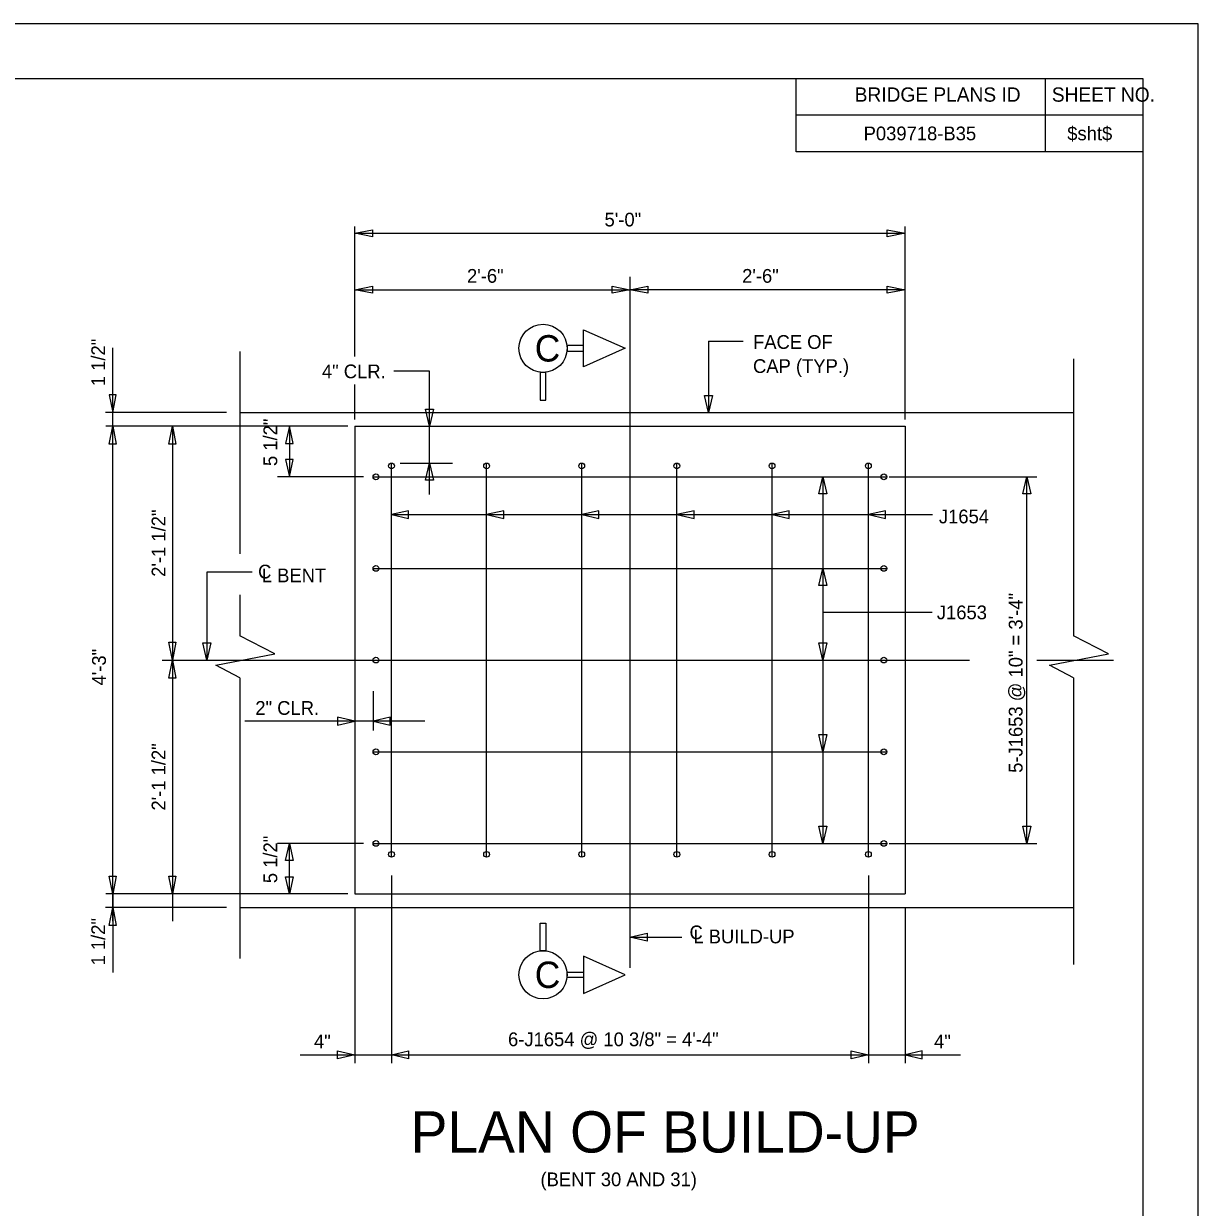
# Model space of a CAD drawing. Extents: x -133.1 to -97, y -58.4 to -36.4.
# Drawn here: x -107.81 to -97.14, y -47.16 to -36.4 of the extents above; entities that cross this region are included whole.
import ezdxf

# ---------------------------------------------------------------- set-up
doc = ezdxf.new("R2010")
doc.units = 0
for name, color, linetype in [('BR_AUTO DIMENSION', 7, 'Continuous'), ('BR_BORDER LINES', 7, 'Continuous'), ('BR_CENTER LINES', 7, 'Continuous'), ('BR_CONCRETE', 7, 'Continuous'), ('BR_REBAR', 7, 'Continuous'), ('BR_TEXT', 7, 'Continuous'), ('Default', 7, 'Continuous'), ('Level 31', 7, 'Continuous')]:
    doc.layers.add(name, color=color, linetype=linetype)

msp = doc.modelspace()

# ---------------------------------------------------------------- linework, layer by layer
at = {"layer": 'BR_AUTO DIMENSION'}
for p, q in [((-104.806, -39.424), (-104.806, -38.242)), ((-104.806, -38.304), (-99.806, -38.304)), ((-99.806, -39.997), (-99.806, -38.242)), ((-102.306, -38.699), (-102.306, -39.063)), ((-104.806, -38.817), (-102.306, -38.817)), ((-99.806, -38.817), (-102.306, -38.817)), ((-107.005, -40.059), (-107.005, -39.345)), ((-101.592, -39.284), (-101.592, -39.934)), ((-101.592, -39.284), (-101.275, -39.284)), ((-104.126, -39.559), (-104.45, -39.559)), ((-104.126, -40.68), (-104.126, -39.559)), ((-104.806, -39.997), (-104.806, -39.678)), ((-107.005, -44.559), (-107.005, -39.809)), ((-105.97, -39.934), (-107.071, -39.934)), ((-104.868, -40.059), (-107.067, -40.059)), ((-106.463, -40.059), (-106.463, -42.184)), ((-105.4, -40.059), (-105.4, -40.518)), ((-104.394, -40.393), (-103.919, -40.393)), ((-104.727, -40.518), (-105.507, -40.518)), ((-100.552, -40.518), (-100.552, -43.851)), ((-99.951, -40.518), (-98.608, -40.518)), ((-98.7, -43.851), (-98.7, -40.518)), ((-104.472, -40.862), (-99.555, -40.862)), ((-106.149, -41.385), (-106.149, -42.184)), ((-105.737, -41.385), (-106.149, -41.385)), ((-100.552, -41.748), (-99.559, -41.748)), ((-106.52, -42.184), (-106.384, -42.184)), ((-106.463, -42.184), (-106.463, -44.559)), ((-104.639, -42.468), (-104.639, -42.823)), ((-104.17, -42.739), (-105.805, -42.739)), ((-104.727, -43.851), (-105.507, -43.851)), ((-105.4, -44.309), (-105.4, -43.851)), ((-99.951, -43.851), (-98.608, -43.851)), ((-104.472, -44.142), (-104.472, -45.847)), ((-100.139, -44.142), (-100.139, -45.847)), ((-104.868, -44.309), (-107.067, -44.309)), ((-107.005, -44.309), (-107.005, -45.023)), ((-105.97, -44.434), (-107.071, -44.434)), ((-104.806, -44.434), (-104.806, -45.847)), ((-99.806, -44.434), (-99.806, -45.847)), ((-102.306, -44.704), (-101.834, -44.704)), ((-105.302, -45.772), (-99.301, -45.772))]:
    msp.add_line(p, q, dxfattribs=at)
for points in [[(-104.643, -38.336), (-104.806, -38.304), (-104.643, -38.273)], [(-99.968, -38.273), (-99.806, -38.304), (-99.968, -38.336)], [(-104.643, -38.848), (-104.806, -38.817), (-104.643, -38.785)], [(-102.468, -38.785), (-102.306, -38.817), (-102.468, -38.848)], [(-102.143, -38.848), (-102.306, -38.817), (-102.143, -38.785)], [(-99.968, -38.785), (-99.806, -38.817), (-99.968, -38.848)], [(-107.036, -39.772), (-107.005, -39.934), (-106.974, -39.772)], [(-101.556, -39.778), (-101.592, -39.934), (-101.628, -39.778)], [(-104.09, -39.903), (-104.126, -40.059), (-104.162, -39.903)], [(-107.036, -40.222), (-107.005, -40.059), (-106.974, -40.222)], [(-106.494, -40.222), (-106.463, -40.059), (-106.432, -40.222)], [(-105.364, -40.215), (-105.4, -40.059), (-105.436, -40.215)], [(-105.436, -40.362), (-105.4, -40.518), (-105.364, -40.362)], [(-104.162, -40.549), (-104.126, -40.393), (-104.09, -40.549)], [(-100.588, -40.674), (-100.552, -40.518), (-100.516, -40.674)], [(-98.736, -40.674), (-98.7, -40.518), (-98.664, -40.674)], [(-104.316, -40.826), (-104.472, -40.862), (-104.316, -40.898)], [(-103.452, -40.826), (-103.608, -40.862), (-103.452, -40.898)], [(-102.587, -40.826), (-102.743, -40.862), (-102.587, -40.898)], [(-101.723, -40.826), (-101.879, -40.862), (-101.723, -40.898)], [(-100.858, -40.826), (-101.014, -40.862), (-100.858, -40.898)], [(-99.983, -40.826), (-100.139, -40.862), (-99.983, -40.898)], [(-100.588, -41.507), (-100.552, -41.351), (-100.516, -41.507)], [(-106.432, -42.022), (-106.463, -42.184), (-106.494, -42.022)], [(-106.113, -42.028), (-106.149, -42.184), (-106.185, -42.028)], [(-100.516, -42.028), (-100.552, -42.184), (-100.588, -42.028)], [(-106.494, -42.347), (-106.463, -42.184), (-106.432, -42.347)], [(-104.962, -42.775), (-104.806, -42.739), (-104.962, -42.703)], [(-104.483, -42.703), (-104.639, -42.739), (-104.483, -42.775)], [(-100.516, -42.862), (-100.552, -43.018), (-100.588, -42.862)], [(-100.516, -43.695), (-100.552, -43.851), (-100.588, -43.695)], [(-98.664, -43.695), (-98.7, -43.851), (-98.736, -43.695)], [(-105.436, -44.007), (-105.4, -43.851), (-105.364, -44.007)], [(-106.974, -44.147), (-107.005, -44.309), (-107.036, -44.147)], [(-106.432, -44.147), (-106.463, -44.309), (-106.494, -44.147)], [(-105.364, -44.153), (-105.4, -44.309), (-105.436, -44.153)], [(-107.036, -44.597), (-107.005, -44.434), (-106.974, -44.597)], [(-102.15, -44.74), (-102.306, -44.704), (-102.15, -44.668)], [(-104.962, -45.736), (-104.806, -45.772), (-104.962, -45.808)], [(-104.316, -45.808), (-104.472, -45.772), (-104.316, -45.736)], [(-100.295, -45.736), (-100.139, -45.772), (-100.295, -45.808)], [(-99.65, -45.736), (-99.806, -45.772), (-99.65, -45.808)]]:
    msp.add_lwpolyline(points, close=True, dxfattribs=at)
at = {"layer": 'BR_BORDER LINES'}
for p, q in [((-97.642, -36.899), (-131.308, -36.899)), ((-100.794, -37.565), (-100.794, -36.899)), ((-98.528, -37.565), (-98.528, -36.899)), ((-97.642, -57.899), (-97.642, -36.899)), ((-100.794, -37.228), (-97.642, -37.228)), ((-98.528, -37.228), (-97.642, -37.228)), ((-97.642, -37.565), (-100.794, -37.565))]:
    msp.add_line(p, q, dxfattribs=at)
at = {"layer": 'BR_CENTER LINES'}
for p, q in [((-102.306, -39.063), (-102.306, -44.981)), ((-106.555, -42.184), (-99.221, -42.184)), ((-98.609, -42.184), (-97.913, -42.184))]:
    msp.add_line(p, q, dxfattribs=at)
at = {"layer": 'BR_CONCRETE'}
for p, q in [((-105.85, -39.934), (-98.276, -39.934)), ((-104.806, -40.059), (-99.806, -40.059)), ((-104.806, -40.059), (-104.806, -44.309)), ((-99.806, -40.059), (-99.806, -44.309)), ((-104.806, -44.309), (-99.806, -44.309)), ((-105.85, -44.434), (-98.276, -44.434))]:
    msp.add_line(p, q, dxfattribs=at)
at = {"layer": 'BR_REBAR'}
for p, q in [((-104.472, -43.976), (-104.472, -40.393)), ((-103.608, -43.976), (-103.608, -40.393)), ((-102.743, -43.976), (-102.743, -40.393)), ((-101.879, -43.976), (-101.879, -40.393)), ((-101.014, -43.976), (-101.014, -40.393)), ((-100.139, -43.976), (-100.139, -40.393)), ((-104.639, -40.518), (-99.972, -40.518)), ((-104.639, -41.351), (-99.972, -41.351)), ((-104.639, -42.184), (-99.972, -42.184)), ((-104.639, -43.018), (-99.972, -43.018)), ((-104.639, -43.851), (-99.972, -43.851))]:
    msp.add_line(p, q, dxfattribs=at)
for centre, radius in [((-104.472, -40.419), 0.0261), ((-103.608, -40.419), 0.0261), ((-102.743, -40.419), 0.0261), ((-101.879, -40.419), 0.0261), ((-101.014, -40.419), 0.0261), ((-100.139, -40.419), 0.0261), ((-104.613, -40.518), 0.026), ((-99.998, -40.518), 0.026), ((-104.613, -41.351), 0.026), ((-99.998, -41.351), 0.026), ((-104.613, -42.184), 0.026), ((-99.998, -42.184), 0.026), ((-104.613, -43.018), 0.026), ((-99.998, -43.018), 0.026), ((-104.613, -43.851), 0.026), ((-99.998, -43.851), 0.026), ((-104.472, -43.95), 0.0261), ((-103.608, -43.95), 0.0261), ((-102.743, -43.95), 0.0261), ((-101.879, -43.95), 0.0261), ((-101.014, -43.95), 0.0261), ((-100.139, -43.95), 0.0261)]:
    msp.add_circle(centre, radius, dxfattribs=at)
at = {"layer": 'BR_TEXT'}
for points in [[(-102.726, -39.182), (-102.35, -39.35), (-102.726, -39.519)], [(-102.876, -39.375), (-102.726, -39.375), (-102.726, -39.325), (-102.876, -39.325)], [(-103.12, -39.82), (-103.07, -39.82), (-103.07, -39.569), (-103.12, -39.569)], [(-103.12, -44.576), (-103.07, -44.576), (-103.07, -44.826), (-103.12, -44.826)], [(-102.726, -45.214), (-102.35, -45.045), (-102.726, -44.876)], [(-102.876, -45.02), (-102.726, -45.02), (-102.726, -45.07), (-102.876, -45.07)]]:
    msp.add_lwpolyline(points, close=True, dxfattribs=at)
for centre in [(-103.095, -39.35), (-103.095, -45.045)]:
    msp.add_circle(centre, 0.219, dxfattribs=at)
at = {"layer": 'Default'}
for p, q in [((-105.85, -39.38), (-105.85, -41.219)), ((-98.276, -39.445), (-98.276, -41.963)), ((-105.85, -41.591), (-105.85, -41.963)), ((-105.85, -42.346), (-105.85, -44.896)), ((-98.276, -42.346), (-98.276, -44.952))]:
    msp.add_line(p, q, dxfattribs=at)
for points in [[(-105.85, -42.346), (-106.067, -42.229), (-105.531, -42.128), (-105.85, -41.963)], [(-98.276, -42.346), (-98.492, -42.229), (-97.956, -42.128), (-98.276, -41.963)]]:
    msp.add_lwpolyline(points, dxfattribs=at)
at = {"layer": 'Level 31'}
msp.add_lwpolyline([(-133.141, -58.399), (-97.141, -58.399), (-97.141, -36.399), (-133.141, -36.399)], close=True, dxfattribs=at)

# ---------------------------------------------------------------- texts
at = {"layer": 'BR_AUTO DIMENSION'}
for s, p in [('5\'-0"', (-102.536, -38.242)), ('2\'-6"', (-103.786, -38.754)), ('2\'-6"', (-101.286, -38.754)), ('FACE OF', (-101.187, -39.355)), ('CAP (TYP.)', (-101.187, -39.574)), ('4" CLR.', (-105.104, -39.622)), ('J1654', (-99.498, -40.941)), ('J1653', (-99.517, -41.813)), ('2" CLR.', (-105.709, -42.682)), ('C', (-101.764, -44.722)), ('L BUILD-UP', (-101.729, -44.759)), ('6-J1654 @ 10 3/8" = 4\'-4"', (-103.413, -45.694)), ('(BENT 30 AND 31)', (-103.118, -46.967))]:
    msp.add_text(s, height=0.125, dxfattribs=at).set_placement(p)
for s, rotation, p in [('2\'-1 1/2"', 90, (-106.526, -41.427)), ('5-J1653 @ 10" = 3\'-4"', 90, (-98.738, -43.209)), ('4\'-3"', 90, (-107.067, -42.415)), ('2\'-1 1/2"', 90, (-106.526, -43.552)), ('4"', 360, (-105.176, -45.713)), ('4"', 360, (-99.542, -45.713))]:
    msp.add_text(s, height=0.125, rotation=rotation, dxfattribs=at).set_placement(p)
at = {"layer": 'BR_TEXT'}
for s, height, p in [('BRIDGE PLANS ID', 0.13, (-100.263, -37.108)), ('SHEET NO.', 0.13, (-98.472, -37.108)), ('P039718-B35', 0.125, (-100.182, -37.459)), ('$sht$', 0.125, (-98.332, -37.459)), ('C', 0.24, (-103.17, -39.47)), ('C', 0.24, (-103.17, -45.165)), ('PLAN OF BUILD-UP', 0.375, (-104.298, -46.661))]:
    msp.add_text(s, height=height, dxfattribs=at).set_placement(p)
for s, rotation, p in [('1 1/2"', 90, (-107.074, -39.694)), ('5 1/2"', 90, (-105.51, -40.42)), ('C', 360, (-105.684, -41.442)), ('L BENT', 360, (-105.65, -41.477)), ('5 1/2"', 90, (-105.51, -44.212)), ('1 1/2"', 90, (-107.074, -44.96))]:
    msp.add_text(s, height=0.125, rotation=rotation, dxfattribs=at).set_placement(p)

doc.saveas('drawing.dxf')
